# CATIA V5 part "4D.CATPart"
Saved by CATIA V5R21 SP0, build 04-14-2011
Part number: Part1
Material "China Blue": density 7860 kg/m3, Young's modulus 2e+11 Pa, Poisson ratio 0.266
Bounding box of the stored display mesh (mm): x -100 to 100, y -100 to 100, z -100 to 100
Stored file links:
  K:\CATIA\4 Dimenssion\4D.CATPart
  C:\Program Files (x86)\Dassault Systemes\B21\intel_a\startup\materials\blue_env_512x512.jpg
  C:\Program Files (x86)\Dassault Systemes\B21\intel_a\startup\materials\yellow_env_512x512.jpg
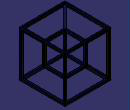
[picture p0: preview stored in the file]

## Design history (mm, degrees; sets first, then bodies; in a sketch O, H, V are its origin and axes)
AxisSystem1: origin (0, 0, 0), X (1, 0, 0), Y (0, 1, 0), Z (0, 0, 1)
Body1 (main body)
  Sketch1 on yz-plane, origin (0, 0, 0), H (0, 1, 0), V (0, 0, 1)
    line L1 (50, 50) -> (50, -50)
    line L2 (50, -50) -> (-50, -50)
    line L3 (-50, -50) -> (-50, 50)
    line L4 (-50, 50) -> (50, 50)
    line L5 (40, 40) -> (40, -40)
    line L6 (40, -40) -> (-40, -40)
    line L7 (-40, -40) -> (-40, 40)
    line L8 (-40, 40) -> (40, 40)
    length L1 = 100
    length L4 = 100
    length L5 = 80
    length L8 = 80
    vertical: L1 V, L3 V, L5 V, L7 V
    horizontal: L2 H, L4 H, L6 H, L8 H
    equidistance: L1 L3 O, L2 L4 O, L5 L7 O, L6 L8 O
  Pad1: profile Sketch1, direction (1, 0, 0), length 50, mirrored extent
  Sketch2 on face of Pad1 from Sketch1.L1, origin (0, 50, 0), H (-1, 0, 0), V (0, 0, 1)
    line L1 (40, 40) -> (40, -40)
    line L2 (40, -40) -> (-40, -40)
    line L3 (-40, -40) -> (-40, 40)
    line L4 (-40, 40) -> (40, 40)
    length L1 = 80
    length L4 = 80
    vertical: L1 V, L3 V
    horizontal: L2 H, L4 H
    equidistance: L1 L3 O, L2 L4 O
  Pocket1: profile Sketch2, direction (0, -1, 0), through (limit type 3)
  Sketch3 on face of Pad1 from Sketch1.L4, origin (0, 0, 50), H (1, 0, 0), V (0, 1, 0)
    line L1 (40, 40) -> (40, -40)
    line L2 (40, -40) -> (-40, -40)
    line L3 (-40, -40) -> (-40, 40)
    line L4 (-40, 40) -> (40, 40)
    length L1 = 80
    length L4 = 80
    vertical: L1 V, L3 V
    horizontal: L2 H, L4 H
    equidistance: L1 L3 O, L2 L4 O
  Pocket2: profile Sketch3, direction (0, 0, -1), through (limit type 3)
  Sketch4 on yz-plane, origin (0, 0, 0), H (0, 1, 0), V (0, 0, 1)
    line L1 (100, 100) -> (100, -100)
    line L2 (100, -100) -> (-100, -100)
    line L3 (-100, -100) -> (-100, 100)
    line L4 (-100, 100) -> (100, 100)
    line L5 (90, 90) -> (90, -90)
    line L6 (90, -90) -> (-90, -90)
    line L7 (-90, -90) -> (-90, 90)
    line L8 (-90, 90) -> (90, 90)
    length L1 = 200
    length L4 = 200
    length L5 = 180
    length L8 = 180
    vertical: L1 V, L3 V, L5 V, L7 V
    horizontal: L2 H, L4 H, L6 H, L8 H
    equidistance: L1 L3 O, L2 L4 O, L5 L7 O, L6 L8 O
  Pad2: profile Sketch4, direction (1, 0, 0), length 100, mirrored extent
  Sketch5 on face of Pad2 from Sketch4.L1, origin (0, 100, 0), H (-1, 0, 0), V (0, 0, 1)
    line L1 (90, 90) -> (90, -90)
    line L2 (90, -90) -> (-90, -90)
    line L3 (-90, -90) -> (-90, 90)
    line L4 (-90, 90) -> (90, 90)
    length L1 = 180
    length L4 = 180
    vertical: L1 V, L3 V
    horizontal: L2 H, L4 H
    equidistance: L1 L3 O, L2 L4 O
  Pocket3: profile Sketch5, direction (0, -1, 0), length 20
  Mirror1: of Pocket3, about zx-plane
  Sketch6 on face of Pad2 from Sketch4.L4, origin (0, 0, 100), H (1, 0, 0), V (0, 1, 0)
    line L1 (90, 90) -> (90, -90)
    line L2 (90, -90) -> (-90, -90)
    line L3 (-90, -90) -> (-90, 90)
    line L4 (-90, 90) -> (90, 90)
    length L1 = 180
    length L4 = 180
    vertical: L1 V, L3 V
    horizontal: L2 H, L4 H
    equidistance: L1 L3 O, L2 L4 O
  Pocket4: profile Sketch6, direction (0, 0, -1), length 20
  Mirror2: of Pocket4, about xy-plane
  Point1: (10, 0, 0), relative to vertex [start face of Pad1 | face of Pad1 from Sketch1.L1 | face of Pad1 from Sketch1.L4]
  Point2: (0, -10, 0), relative to vertex [start face of Pad1 | face of Pad1 from Sketch1.L1 | face of Pad1 from Sketch1.L4]
  Point3: (0, 0, -10), relative to vertex [start face of Pad1 | face of Pad1 from Sketch1.L1 | face of Pad1 from Sketch1.L4]
  Plane1: type 3Points, Element1 Point3, Element2 Point1, Element3 Point2
  Plane2: type Offset, RefPlane Plane1, Offset 8
  Sketch7 on Plane2, origin (-42.0479, 42.0479, 42.0479), H (0.7071, 0.7071, 0), V (0.4082, -0.4082, 0.8165)
    line L1 (5, 5) -> (5, -5)
    line L2 (5, -5) -> (-5, -5)
    line L3 (-5, -5) -> (-5, 5)
    line L4 (-5, 5) -> (5, 5)
    length L1 = 10
    length L4 = 10
    vertical: L1 V, L3 V
    horizontal: L2 H, L4 H
    equidistance: L1 L3 O, L2 L4 O
  Pad3: profile Sketch7, direction (-0.5774, 0.5774, 0.5774), up to the existing solid (limit type 3)
  CircPattern1: of Pad3, instances 4, angular step 90, axis from edge [ZX plane of AxisSystem1 | YZ plane of AxisSystem1]
  Point4: (0, 0, 10), relative to vertex [start face of Pad1 | face of Pad1 from Sketch1.L2 | face of Pad1 from Sketch1.L1], in AxisSystem1
  Point5: (0, -10, 0), relative to vertex [start face of Pad1 | face of Pad1 from Sketch1.L2 | face of Pad1 from Sketch1.L1], in AxisSystem1
  Point6: (10, 0, 0), relative to vertex [start face of Pad1 | face of Pad1 from Sketch1.L2 | face of Pad1 from Sketch1.L1], in AxisSystem1
  Plane3: type 3Points, Element1 Point5, Element2 Point6, Element3 Point4
  Plane4: type Offset, RefPlane Plane3, Offset 8
  Sketch8 on Plane4, origin (-42.0479, 42.0479, -42.0479), H (0.7071, 0.7071, 0), V (-0.4082, 0.4082, 0.8165)
    line L1 (5, 5) -> (5, -5)
    line L2 (5, -5) -> (-5, -5)
    line L3 (-5, -5) -> (-5, 5)
    line L4 (-5, 5) -> (5, 5)
    length L1 = 10
    length L2 = 10
    vertical: L1 V, L3 V
    horizontal: L2 H, L4 H
    equidistance: L1 L3 O, L2 L4 O
  Pad4: profile Sketch8, direction (-0.5774, 0.5774, -0.5774), up to the existing solid (limit type 3)
  CircPattern2: of Pad4, instances 4, angular step 90, axis from xy-plane
  Fillet1: radius 2, on end face of Pad2; face of Pad2 from Sketch4.L2; face of Pad2 from Sketch4.L4; face of Pad2 from Sketch4.L1; face of Pad2 from Sketch4.L3; start face of Pad2
  Fillet2: radius 2, on face of Pad1 from Sketch1.L1; end face of Pad1; face of Pad1 from Sketch1.L3; start face of Pad1; face of Pad1 from Sketch1.L2; face of Pad1 from Sketch1.L4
